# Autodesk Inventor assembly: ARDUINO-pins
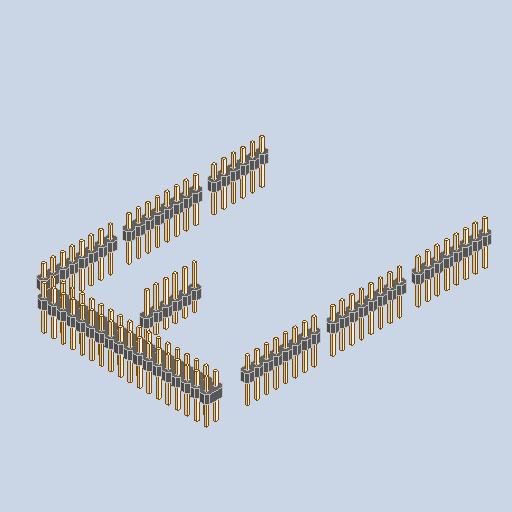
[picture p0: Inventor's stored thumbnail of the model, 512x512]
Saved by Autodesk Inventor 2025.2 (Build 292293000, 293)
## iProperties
Created: 2025-04
Part Number: ARDUINO-pins
Description: PART--DESC
Document SubType Name: Assembly
Designer: BennF
Author: BennF
Revision Number: NONE
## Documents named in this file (9)
- C:\Users\BennF\Nextcloud\Benutzer\CNC JarBeRi\existing parts\Electronics\RepRap A4988 Shied (USE WITHOUT ARDUINO)\reprap-a4988-1.snapshot.1\RepRap\RepRap\ARDUINO-pins.iam
- C:\Users\BennF\Nextcloud\Benutzer\CNC JarBeRi\existing parts\Electronics\RepRap A4988 Shied (USE WITHOUT ARDUINO)\reprap-a4988-1.snapshot.1\RepRap\RepRap\8M_1.iam
- C:\Users\BennF\Nextcloud\Benutzer\CNC JarBeRi\existing parts\Electronics\RepRap A4988 Shied (USE WITHOUT ARDUINO)\reprap-a4988-1.snapshot.1\RepRap\RepRap\8M_2.iam
- C:\Users\BennF\Nextcloud\Benutzer\CNC JarBeRi\existing parts\Electronics\RepRap A4988 Shied (USE WITHOUT ARDUINO)\reprap-a4988-1.snapshot.1\RepRap\RepRap\8M_3.iam
- C:\Users\BennF\Nextcloud\Benutzer\CNC JarBeRi\existing parts\Electronics\RepRap A4988 Shied (USE WITHOUT ARDUINO)\reprap-a4988-1.snapshot.1\RepRap\RepRap\8M_4.iam
- C:\Users\BennF\Nextcloud\Benutzer\CNC JarBeRi\existing parts\Electronics\RepRap A4988 Shied (USE WITHOUT ARDUINO)\reprap-a4988-1.snapshot.1\RepRap\RepRap\8M_5.iam
- C:\Users\BennF\Nextcloud\Benutzer\CNC JarBeRi\existing parts\Electronics\RepRap A4988 Shied (USE WITHOUT ARDUINO)\reprap-a4988-1.snapshot.1\RepRap\RepRap\6M.iam
- C:\Users\BennF\Nextcloud\Benutzer\CNC JarBeRi\existing parts\Electronics\RepRap A4988 Shied (USE WITHOUT ARDUINO)\reprap-a4988-1.snapshot.1\RepRap\RepRap\18x2M.iam
- C:\Users\BennF\Nextcloud\Benutzer\CNC JarBeRi\existing parts\Electronics\RepRap A4988 Shied (USE WITHOUT ARDUINO)\reprap-a4988-1.snapshot.1\RepRap\RepRap\6M_1.iam
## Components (8 placed, 3 different names)
1. 8M [sub-assembly]
2. 8M:1 [sub-assembly]
3. 8M:2 [sub-assembly]
4. 8M:3 [sub-assembly]
5. 8M:4 [sub-assembly]
6. 6M [sub-assembly]
7. 18x2M [sub-assembly]
8. 6M:1 [sub-assembly]
